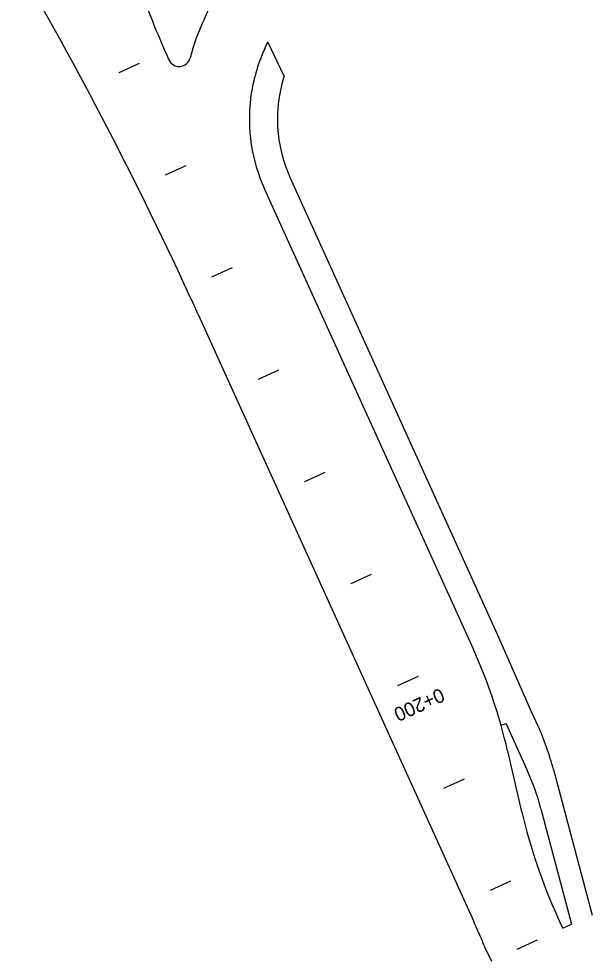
# Model space of a CAD drawing. Extents: x 6503541 to 6503743, y 5888004 to 5888145.
# Drawn here: x 6503637.804 to 6503639.03, y 5888065.208 to 5888067.223 of the extents above; entities that cross this region are included whole.
import ezdxf

# ---------------------------------------------------------------- set-up
doc = ezdxf.new("R2010")
doc.units = 0
doc.layers.add('12', color=7, linetype='Continuous')

msp = doc.modelspace()

# ---------------------------------------------------------------- linework, layer by layer
at = {"layer": '12'}
for p, q in [((6503638.201, 5888067.2226), (6503638.2116, 5888067.2451)), ((6503638.3302, 5888067.1589), (6503638.337, 5888067.1736)), ((6503638.3715, 5888067.0999), (6503638.337, 5888067.1736)), ((6503638.8281, 5888065.9062), (6503638.3836, 5888066.8851)), ((6503638.7735, 5888065.8814), (6503638.3294, 5888066.8594)), ((6503638.1879, 5888066.5906), (6503638.7772, 5888065.2928)), ((6503638.9009, 5888065.7408), (6503638.8281, 5888065.9062)), ((6503638.9141, 5888065.7118), (6503638.9009, 5888065.7408)), ((6503638.8353, 5888065.7128), (6503638.8463, 5888065.716)), ((6503638.8906, 5888065.6184), (6503638.8463, 5888065.716)), ((6503638.8798, 5888065.5275), (6503638.8496, 5888065.6575)), ((6503638.9477, 5888065.6177), (6503639.0303, 5888065.3065)), ((6503638.9208, 5888065.5337), (6503638.9862, 5888065.2873)), ((6503638.9673, 5888065.2785), (6503638.9562, 5888065.3031)), ((6503638.9673, 5888065.2785), (6503638.9862, 5888065.2873)), ((6503638.7867, 5888065.2708), (6503638.7893, 5888065.2646)), ((6503638.8004, 5888065.2391), (6503638.8147, 5888065.2082))]:
    msp.add_line(p, q, dxfattribs=at)
for points in [[(6503638.0188, 5888067.1079), (6503638.0625, 5888067.1278)], [(6503638.1181, 5888066.8894), (6503638.1618, 5888066.9093)], [(6503638.2173, 5888066.6709), (6503638.261, 5888066.6907)], [(6503638.3165, 5888066.4524), (6503638.3602, 5888066.4722)], [(6503638.4158, 5888066.2338), (6503638.4595, 5888066.2537)], [(6503638.515, 5888066.0153), (6503638.5587, 5888066.0352)], [(6503638.6579, 5888065.8166), (6503638.6142, 5888065.7968)], [(6503638.7134, 5888065.5783), (6503638.7571, 5888065.5981)], [(6503638.8127, 5888065.3597), (6503638.8564, 5888065.3796)], [(6503638.8699, 5888065.2337), (6503638.9136, 5888065.2536)]]:
    msp.add_lwpolyline(points, dxfattribs=at)
for centre, radius, start, end in [((6503630.5394, 5888063.1176), 8.4, 24.42189, 30.13249), ((6503639.7635, 5888067.8805), 1.8, 198.7113, 204.4756), ((6503638.6572, 5888067.0083), 0.504, 154.8374, 165.0212), ((6503638.6572, 5888067.0083), 0.36, 155.2546, 157.7748), ((6503638.1471, 5888067.1447), 0.024, 204.4756, 345.0212), ((6503638.6572, 5888067.0083), 0.36, 157.7748, 166.1162), ((6503638.6572, 5888067.0083), 0.3, 162.2194, 204.4219), ((6503638.6572, 5888067.0083), 0.36, 166.1162, 172.8706), ((6503638.6572, 5888067.0083), 0.36, 172.8706, 204.4219), ((6503637.6808, 5888065.3853), 1.2, 13.112, 24.4219), ((6503638.3678, 5888065.4637), 0.6, 14.8672, 24.4219), ((6503638.3989, 5888065.3951), 0.54, 14.8672, 24.4219), ((6503640.0486, 5888065.7997), 1.2, 193.112, 204.4483), ((6503638.1216, 5888064.9951), 0.72, 22.5145, 24.4219), ((6503639.4544, 5888065.5403), 0.72, 202.5145, 204.7242)]:
    msp.add_arc(centre, radius, start, end, dxfattribs=at)

# ---------------------------------------------------------------- texts
msp.add_text('0+200', height=0.03, rotation=204.4219, dxfattribs=at).set_placement((6503638.7058, 5888065.793))

doc.saveas('drawing.dxf')
